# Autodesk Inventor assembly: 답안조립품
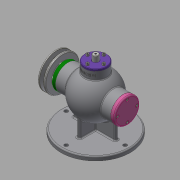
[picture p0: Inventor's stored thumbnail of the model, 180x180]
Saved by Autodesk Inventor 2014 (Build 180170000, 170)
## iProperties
Created: 2020-08
Part Number: 답안조립품
Document SubType Name: Assembly
Designer: kh
Author: kh
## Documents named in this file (18)
- C:\Users\kh\Desktop\700806V1023\답안조립품.iam
- C:\Users\kh\Desktop\700806V1023\본체.ipt
- C:\Users\kh\Desktop\700806V1023\V-벨트풀리.ipt
- C:\Users\kh\Desktop\700806V1023\너트 M8.ipt
- C:\Users\kh\Desktop\700806V1023\뒤커버.ipt
- C:\Users\kh\Desktop\700806V1023\멈춤링 15x1.ipt
- C:\Users\kh\Desktop\700806V1023\멈춤링 35x1.6.ipt
- 멈춤링 35x1.6.ipt
- C:\Users\kh\Desktop\700806V1023\베어링 6202.ipt
- 베어링 6202.ipt
- C:\Users\kh\Desktop\700806V1023\볼트 M4.ipt
- C:\Users\kh\Desktop\700806V1023\상부커버.ipt
- C:\Users\kh\Desktop\700806V1023\슬라이드.ipt
- C:\Users\kh\Desktop\700806V1023\앞커버.ipt
- C:\Users\kh\Desktop\700806V1023\오일 실 15 30 7.ipt
- C:\Users\kh\Desktop\700806V1023\칼라.ipt
- C:\Users\kh\Desktop\700806V1023\키 3x3x12.ipt
- C:\Users\kh\Desktop\700806V1023\편심축.ipt
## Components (1 placed, 1 different names)
1. V-벨트풀리:1 — Insert:16, Mate:2, Insert:17
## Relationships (3: Insert 2, Mate 1)
- Insert:16: V-벨트풀리:1
- Mate:2: V-벨트풀리:1
- Insert:17: V-벨트풀리:1
